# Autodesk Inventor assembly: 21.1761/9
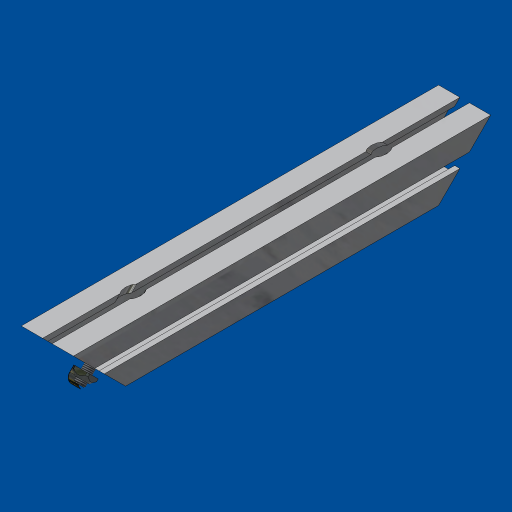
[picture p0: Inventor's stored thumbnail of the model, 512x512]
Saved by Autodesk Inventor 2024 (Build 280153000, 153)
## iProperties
Created: 2024-02
Part Number: 21.1761/9
Document SubType Name: Assembly
Designer: amoles
Author: amoles
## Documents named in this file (4)
- L:\INVENTOR LIBRARIES\PARTS LIBRARY\FEET WHEELS FLOOR FASTENING SUPPORTS\21.1761_9 STRENGTHENING ELEMENT 45F.iam
- L:\INVENTOR LIBRARIES\PARTS LIBRARY\FEET WHEELS FLOOR FASTENING SUPPORTS\SUBCOMPONENTS\21.1761_9_1 STRENGTHENING ELEMENT 45F PROFILE.ipt
- L:\INVENTOR LIBRARIES\PARTS LIBRARY\FASTENING ELEMENTS\SCREWS CAP\21.1208 M8X35.ipt
- L:\INVENTOR LIBRARIES\PARTS LIBRARY\FASTENING ELEMENTS\NUTS\21.1351_2 M8 SQUARE NUT POS FXG.ipt
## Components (5 placed, 3 different names)
1. 21.1761_9_1 STRENGTHENING ELEMENT 45F PROFILE:1 — Insert:1, Insert:2, Mate:1, Angle:1, Mate:4, Angle:2
2. 21.1208  M8 x 35:1 — Insert:1, Mate:2
3. 21.1208  M8 x 35:2 — Insert:2, Mate:3
4. 21.1351_2 M8 SQUARE NUT POS FXG:1 — Mate:1, Mate:2, Angle:1
5. 21.1351_2 M8 SQUARE NUT POS FXG:2 — Mate:3, Mate:4, Angle:2
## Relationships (8: Mate 4, Insert 2, Angle 2)
- Insert:1: 21.1761_9_1 STRENGTHENING ELEMENT 45F PROFILE:1 ↔ 21.1208  M8 x 35:1
- Insert:2: 21.1761_9_1 STRENGTHENING ELEMENT 45F PROFILE:1 ↔ 21.1208  M8 x 35:2
- Mate:1: 21.1761_9_1 STRENGTHENING ELEMENT 45F PROFILE:1 ↔ 21.1351_2 M8 SQUARE NUT POS FXG:1
- Mate:2: 21.1208  M8 x 35:1 ↔ 21.1351_2 M8 SQUARE NUT POS FXG:1
- Angle:1: 21.1761_9_1 STRENGTHENING ELEMENT 45F PROFILE:1 ↔ 21.1351_2 M8 SQUARE NUT POS FXG:1
- Mate:3: 21.1208  M8 x 35:2 ↔ 21.1351_2 M8 SQUARE NUT POS FXG:2
- Mate:4: 21.1761_9_1 STRENGTHENING ELEMENT 45F PROFILE:1 ↔ 21.1351_2 M8 SQUARE NUT POS FXG:2
- Angle:2: 21.1761_9_1 STRENGTHENING ELEMENT 45F PROFILE:1 ↔ 21.1351_2 M8 SQUARE NUT POS FXG:2
